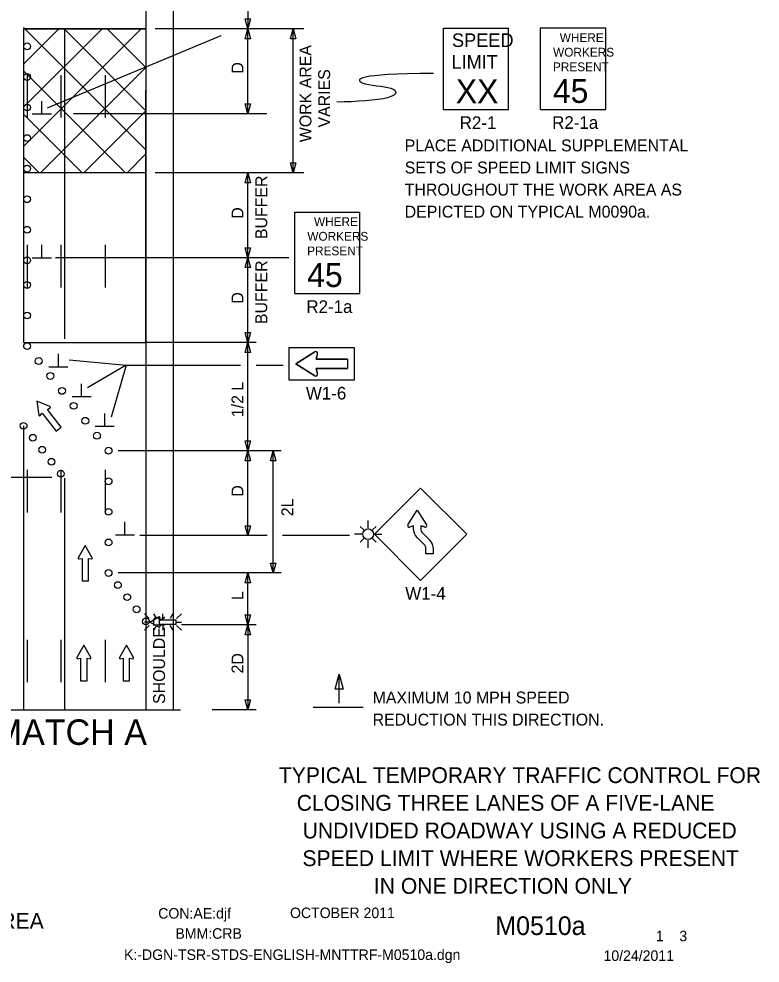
# Model space of a CAD drawing. Extents: x 16730 to 19504, y 5697 to 6911.
# Drawn here: x 17009 to 17445, y 5932 to 6488 of the extents above; entities that cross this region are included whole.
import ezdxf

# ---------------------------------------------------------------- set-up
doc = ezdxf.new("R2010")
doc.units = 0
for name, color, linetype in [('ALI_LEGAL_EX', 7, 'Continuous'), ('BORDER', 7, 'Continuous'), ('BORDER_SIGNAL_WO', 7, 'Continuous'), ('MT_SCRATCH_LEVEL_A', 7, 'Continuous'), ('MT_SCRATCH_LEVEL_E', 7, 'Continuous'), ('PAVT_EDGE_EX', 7, 'Continuous'), ('TRAFFIC_SIGNS_PR', 7, 'Continuous'), ('TYPICAL_TEXT_DIMEN_EX', 7, 'Continuous'), ('TYPICAL_TEXT_DIMEN_PR', 7, 'Continuous')]:
    doc.layers.add(name, color=color, linetype=linetype)

msp = doc.modelspace()

# ---------------------------------------------------------------- linework, layer by layer
at = {"layer": 'ALI_LEGAL_EX'}
for points in [[(17013.43, 6454.77), (17013.43, 6429.77)], [(17033.43, 6454.77), (17033.43, 6429.77)], [(17059.43, 6454.77), (17059.43, 6429.77)], [(17013.43, 6354.77), (17013.43, 6329.77)], [(17033.43, 6354.77), (17033.43, 6329.77)], [(17059.43, 6354.77), (17059.43, 6329.77)], [(17013.43, 6222.28), (17013.43, 6197.28)], [(17033.43, 6222.28), (17033.43, 6197.28)], [(17059.43, 6222.28), (17059.43, 6197.28)], [(17013.43, 6122.28), (17013.43, 6097.28)], [(17033.43, 6122.28), (17033.43, 6097.28)], [(17059.43, 6122.28), (17059.43, 6097.28)]]:
    msp.add_lwpolyline(points, dxfattribs=at)
at = {"layer": 'MT_SCRATCH_LEVEL_A'}
for p, q in [((17083.43, 6410.69), (17011.43, 6482.69)), ((17011.43, 6481.95), (17083.43, 6481.95)), ((17083.43, 6481.95), (17011.43, 6481.95)), ((17011.43, 6412.69), (17080.7, 6481.95)), ((17011.43, 6461.23), (17032.15, 6481.95)), ((17011.43, 6435.78), (17057.61, 6481.95)), ((17083.43, 6433.78), (17035.26, 6481.95)), ((17083.43, 6459.23), (17060.72, 6481.95)), ((17071.44, 6397.23), (17011.43, 6457.24)), ((17021.43, 6397.23), (17083.43, 6459.23)), ((17083.43, 6445.95), (17083.43, 6329.72)), ((17083.43, 6361.78), (17083.43, 6445.95)), ((17046.89, 6397.23), (17083.43, 6433.78)), ((17045.98, 6397.23), (17011.43, 6431.78)), ((17020.53, 6397.23), (17011.43, 6406.33)), ((17072.34, 6397.23), (17083.43, 6408.32))]:
    msp.add_line(p, q, dxfattribs=at)
at = {"layer": 'MT_SCRATCH_LEVEL_E'}
for p, q in [((17019.24, 6262.76), (17020.44, 6254.52)), ((17026.95, 6259.58), (17019.24, 6262.76)), ((17019.24, 6262.76), (17020.44, 6254.52)), ((17026.95, 6259.58), (17019.24, 6262.76)), ((17021.24, 6254.27), (17022.44, 6255.61)), ((17021.24, 6254.27), (17022.44, 6255.61)), ((17022.44, 6255.61), (17030.58, 6245.15)), ((17022.44, 6255.61), (17030.58, 6245.15)), ((17025.4, 6257.91), (17026.99, 6258.75)), ((17025.4, 6257.91), (17026.99, 6258.75)), ((17033.54, 6247.44), (17025.4, 6257.91)), ((17033.54, 6247.44), (17025.4, 6257.91)), ((17030.58, 6245.15), (17033.54, 6247.44)), ((17030.58, 6245.15), (17033.54, 6247.44)), ((17047.71, 6177.79), (17043.6, 6170.55)), ((17047.71, 6177.79), (17043.6, 6170.55)), ((17051.85, 6170.55), (17047.71, 6177.79)), ((17051.85, 6170.55), (17047.71, 6177.79)), ((17044.08, 6169.87), (17045.85, 6170.18)), ((17044.08, 6169.87), (17045.85, 6170.18)), ((17045.85, 6170.18), (17045.85, 6156.93)), ((17045.85, 6170.18), (17045.85, 6156.93)), ((17049.6, 6156.93), (17049.6, 6170.18)), ((17049.6, 6170.18), (17051.37, 6169.87)), ((17049.6, 6156.93), (17049.6, 6170.18)), ((17049.6, 6170.18), (17051.37, 6169.87)), ((17045.85, 6156.93), (17049.6, 6156.93)), ((17045.85, 6156.93), (17049.6, 6156.93)), ((17046.87, 6119.02), (17042.76, 6111.78)), ((17046.87, 6119.02), (17042.76, 6111.78)), ((17051.02, 6111.78), (17046.87, 6119.02)), ((17051.02, 6111.78), (17046.87, 6119.02)), ((17071.96, 6119.02), (17067.85, 6111.78)), ((17071.96, 6119.02), (17067.85, 6111.78)), ((17076.11, 6111.78), (17071.96, 6119.02)), ((17076.11, 6111.78), (17071.96, 6119.02)), ((17043.24, 6111.1), (17045.02, 6111.41)), ((17043.24, 6111.1), (17045.02, 6111.41)), ((17045.02, 6111.41), (17045.02, 6098.16)), ((17045.02, 6111.41), (17045.02, 6098.16)), ((17048.76, 6098.16), (17048.76, 6111.41)), ((17048.76, 6111.41), (17050.54, 6111.1)), ((17048.76, 6098.16), (17048.76, 6111.41)), ((17048.76, 6111.41), (17050.54, 6111.1)), ((17068.33, 6111.1), (17070.11, 6111.41)), ((17068.33, 6111.1), (17070.11, 6111.41)), ((17070.11, 6111.41), (17070.11, 6098.16)), ((17070.11, 6111.41), (17070.11, 6098.16)), ((17073.85, 6098.16), (17073.85, 6111.41)), ((17073.85, 6111.41), (17075.63, 6111.1)), ((17073.85, 6098.16), (17073.85, 6111.41)), ((17073.85, 6111.41), (17075.63, 6111.1)), ((17045.02, 6098.16), (17048.76, 6098.16)), ((17045.02, 6098.16), (17048.76, 6098.16)), ((17070.11, 6098.16), (17073.85, 6098.16)), ((17070.11, 6098.16), (17073.85, 6098.16))]:
    msp.add_line(p, q, dxfattribs=at)
for centre, start, end in [((17026.77, 6259.16), 297.9028, 67.6397), ((17026.77, 6259.16), 297.9028, 67.6397), ((17020.89, 6254.59), 188.2915, 317.8304), ((17020.89, 6254.59), 188.2915, 317.8304), ((17044, 6170.33), 150.4248, 279.9638), ((17044, 6170.33), 150.4248, 279.9638), ((17051.44, 6170.33), 260.0362, 29.7731), ((17051.44, 6170.33), 260.0362, 29.7731), ((17043.17, 6111.56), 150.4248, 279.9638), ((17043.17, 6111.56), 150.4248, 279.9638), ((17050.61, 6111.56), 260.0362, 29.7731), ((17050.61, 6111.56), 260.0362, 29.7731), ((17068.26, 6111.56), 150.4248, 279.9638), ((17068.26, 6111.56), 150.4248, 279.9638), ((17075.7, 6111.56), 260.0362, 29.7731), ((17075.7, 6111.56), 260.0362, 29.7731)]:
    msp.add_arc(centre, 0.463, start, end, dxfattribs=at)
at = {"layer": 'PAVT_EDGE_EX'}
for p, q in [((17083.43, 6911.29), (17083.43, 6081.05)), ((17099.43, 6911.29), (17099.43, 6081.05)), ((17011.43, 6481.95), (17011.43, 6329.72)), ((17035.43, 6481.95), (17035.43, 6299.46)), ((17011.43, 6248.17), (17011.43, 6081.05)), ((17035.43, 6217.31), (17035.43, 6081.05))]:
    msp.add_line(p, q, dxfattribs=at)
msp.add_lwpolyline([(17083.43, 6397.23), (17011.43, 6397.23), (17011.43, 6297.23), (17083.43, 6297.23)], close=True, dxfattribs=at)
at = {"layer": 'TRAFFIC_SIGNS_PR'}
for p, q in [((17258.65, 6482.45), (17297.05, 6482.45)), ((17258.65, 6434.45), (17258.65, 6482.45)), ((17297.05, 6434.45), (17297.05, 6482.45)), ((17315.85, 6482.54), (17354.25, 6482.54)), ((17315.85, 6434.54), (17315.85, 6482.54)), ((17354.25, 6434.54), (17354.25, 6482.54)), ((17258.65, 6434.45), (17297.05, 6434.45)), ((17315.85, 6434.54), (17354.25, 6434.54)), ((17171.11, 6374.13), (17209.51, 6374.13)), ((17171.11, 6326.13), (17171.11, 6374.13)), ((17209.51, 6326.13), (17209.51, 6374.13)), ((17171.11, 6326.13), (17209.51, 6326.13)), ((17182.89, 6291.86), (17171.73, 6284.76)), ((17183.73, 6287.56), (17184.57, 6290.62)), ((17171.73, 6284.76), (17182.89, 6277.65)), ((17202.13, 6287.56), (17183.73, 6287.56)), ((17202.13, 6287.56), (17202.13, 6281.96)), ((17184.57, 6278.9), (17183.73, 6281.96)), ((17183.73, 6281.96), (17202.13, 6281.96)), ((17218.04, 6184.39), (17245.2, 6211.55)), ((17272.35, 6184.39), (17245.2, 6211.55)), ((17211.81, 6186.91), (17209.71, 6189.01)), ((17214.33, 6187.95), (17214.33, 6192.45)), ((17216.84, 6186.91), (17218.95, 6189.01)), ((17211.17, 6184.39), (17206.34, 6184.39)), ((17217.48, 6184.39), (17222.36, 6184.39)), ((17245.2, 6157.24), (17218.04, 6184.39)), ((17272.35, 6184.39), (17245.2, 6157.24)), ((17250.67, 6180.93), (17245.95, 6185.64)), ((17245.95, 6185.64), (17250.67, 6180.93)), ((17211.81, 6181.88), (17209.71, 6179.77)), ((17214.33, 6176.43), (17214.33, 6180.84)), ((17216.84, 6181.88), (17218.95, 6179.77)), ((17247.61, 6177.88), (17242.9, 6182.59)), ((17247.61, 6177.87), (17242.9, 6182.59)), ((17082.56, 6137.53), (17085.38, 6134.72)), ((17088, 6137.54), (17089.21, 6135.44)), ((17093.47, 6134.72), (17093.47, 6137.54)), ((17099.26, 6137.54), (17097.63, 6134.72)), ((17101.55, 6134.72), (17104.38, 6137.54)), ((17085.38, 6132.68), (17082.56, 6132.68)), ((17082.56, 6127.83), (17085.38, 6130.65)), ((17089.29, 6130.02), (17088.03, 6127.83)), ((17093.47, 6130.65), (17093.47, 6127.83)), ((17097.6, 6130.65), (17099.23, 6127.83)), ((17101.55, 6132.68), (17104.38, 6132.68)), ((17101.55, 6130.65), (17104.38, 6127.83))]:
    msp.add_line(p, q, dxfattribs=at)
msp.add_lwpolyline([(17206.13, 6275.16), (17167.73, 6275.16), (17167.73, 6294.36), (17206.13, 6294.36)], close=True, dxfattribs=at)
for points in [[(17182.89, 6277.65), (17171.73, 6284.76), (17182.89, 6291.86)], [(17184.57, 6290.62), (17183.73, 6287.56), (17202.13, 6287.56), (17202.13, 6281.96), (17183.73, 6281.96), (17184.57, 6278.9)], [(17237.74, 6189.92), (17243.23, 6198.53), (17248.71, 6189.92)], [(17237.75, 6189.92), (17243.23, 6198.53), (17248.71, 6189.92)], [(17241.08, 6186.9), (17241.07, 6189.27), (17238.71, 6188.62)], [(17241.08, 6186.9), (17241.07, 6189.27), (17238.71, 6188.62)], [(17247.75, 6188.62), (17245.39, 6189.27), (17245.39, 6186.97)], [(17247.75, 6188.62), (17246.91, 6188.85), (17245.39, 6189.27), (17245.39, 6186.97)], [(17252.53, 6176.51), (17252.53, 6172.81), (17248.22, 6172.81), (17248.22, 6176.51)], [(17091.14, 6129.67), (17085.83, 6132.68), (17091.14, 6135.73)], [(17091.64, 6135.37), (17091.41, 6134.07), (17101.14, 6134.07), (17101.14, 6131.33), (17091.41, 6131.33), (17091.64, 6130.02)]]:
    msp.add_lwpolyline(points, dxfattribs=at)
for centre, radius in [((17013.46, 6471.67), 2), ((17013.46, 6453.67), 2), ((17013.46, 6435.67), 2), ((17013.46, 6417.67), 2), ((17013.46, 6399.67), 2), ((17013.46, 6381.67), 2), ((17013.46, 6363.67), 2), ((17013.46, 6345.67), 2), ((17013.46, 6331.18), 2), ((17013.46, 6313.18), 2), ((17013.46, 6295.18), 2), ((17013.46, 6295.18), 2), ((17020.32, 6286.39), 2), ((17027.17, 6277.59), 2), ((17034.03, 6268.8), 2), ((17040.89, 6260), 2), ((17011.38, 6248.24), 2), ((17047.74, 6251.21), 2), ((17054.6, 6242.41), 2), ((17016.87, 6241.19), 2), ((17022.35, 6234.13), 2), ((17061.46, 6233.57), 2), ((17061.46, 6233.57), 2), ((17027.84, 6227.07), 2), ((17033.32, 6220.02), 2), ((17061.46, 6215.57), 2), ((17061.46, 6197.57), 2), ((17214.33, 6184.39), 3.15), ((17061.46, 6179.57), 2), ((17061.46, 6161.57), 2), ((17066.95, 6154.43), 2), ((17072.45, 6147.31), 2), ((17077.95, 6140.18), 2), ((17083.45, 6133.05), 2)]:
    msp.add_circle(centre, radius, dxfattribs=at)
for centre, radius, start, end in [((17183.49, 6290.91), 1.12, 344.6731, 122.4696), ((17183.49, 6290.91), 1.12, 344.6731, 122.4696), ((17183.49, 6278.6), 1.12, 237.5304, 15.3269), ((17183.49, 6278.6), 1.12, 237.5304, 15.3269), ((17238.48, 6189.45), 0.866, 147.7292, 285.3172), ((17238.48, 6189.45), 0.866, 147.7196, 285.3201), ((17228.64, 6195.71), 10.8, 327.5335, 327.5431), ((17241.56, 6178.2), 10.8, 105.3192, 105.32), ((17247.98, 6189.45), 0.866, 254.6148, 32.4712), ((17247.24, 6186.97), 6.17, 180.6181, 225.7875), ((17247.24, 6186.97), 6.17, 180.6245, 225.2313), ((17247.24, 6186.97), 1.85, 180, 225.7875), ((17247.24, 6186.97), 1.85, 179.8762, 225.7877), ((17246.37, 6176.51), 1.85, 0, 47.628), ((17246.37, 6176.51), 6.17, 0, 45.7883), ((17091.31, 6135.43), 0.341, 350.0407, 118.5167), ((17091.31, 6129.97), 0.341, 241.1084, 9.2692)]:
    msp.add_arc(centre, radius, start, end, dxfattribs=at)
at = {"layer": 'TYPICAL_TEXT_DIMEN_PR'}
for p, q in [((17143.43, 6506.95), (17143.43, 6481.95)), ((17143.43, 6481.95), (17141.86, 6487.81)), ((17141.86, 6487.81), (17143.43, 6487.81)), ((17143.43, 6487.81), (17145, 6487.81)), ((17145, 6487.81), (17143.43, 6481.95)), ((17127.61, 6477.78), (17025.37, 6435.27)), ((17176.35, 6481.95), (17088.94, 6481.95)), ((17141.86, 6476.09), (17143.43, 6481.95)), ((17143.43, 6431.95), (17143.43, 6482.6)), ((17143.43, 6481.95), (17145, 6476.09)), ((17168.68, 6476.09), (17170.25, 6481.95)), ((17170.25, 6397.23), (17170.25, 6481.95)), ((17170.25, 6481.95), (17171.82, 6476.09)), ((17143.43, 6476.09), (17141.86, 6476.09)), ((17145, 6476.09), (17143.43, 6476.09)), ((17170.25, 6476.09), (17168.68, 6476.09)), ((17171.82, 6476.09), (17170.25, 6476.09)), ((17022.13, 6431.72), (17022.13, 6439.5)), ((17143.43, 6431.95), (17141.86, 6437.81)), ((17141.86, 6437.81), (17143.43, 6437.81)), ((17143.43, 6437.81), (17145.01, 6437.81)), ((17145.01, 6437.81), (17143.43, 6431.95)), ((17027.76, 6431.72), (17016.51, 6431.72)), ((17154.74, 6431.95), (17040.71, 6431.95)), ((17170.25, 6397.23), (17168.68, 6403.09)), ((17168.68, 6403.09), (17170.25, 6403.09)), ((17170.25, 6403.09), (17171.82, 6403.09)), ((17171.82, 6403.09), (17170.25, 6397.23)), ((17176.35, 6397.23), (17088.94, 6397.23)), ((17141.86, 6391.37), (17143.43, 6397.23)), ((17143.43, 6347.23), (17143.43, 6397.23)), ((17143.43, 6397.23), (17145, 6391.37)), ((17143.43, 6391.37), (17141.86, 6391.37)), ((17145, 6391.37), (17143.43, 6391.37)), ((17022.13, 6347), (17022.13, 6354.78)), ((17143.43, 6347.23), (17141.86, 6353.09)), ((17141.86, 6353.09), (17143.43, 6353.09)), ((17143.43, 6353.09), (17145.01, 6353.09)), ((17145.01, 6353.09), (17143.43, 6347.23)), ((17027.76, 6347), (17016.51, 6347)), ((17167.54, 6347.23), (17030.11, 6347.23)), ((17141.86, 6341.37), (17143.43, 6347.23)), ((17143.43, 6297.23), (17143.43, 6347.23)), ((17143.43, 6347.23), (17145, 6341.37)), ((17143.43, 6341.37), (17141.86, 6341.37)), ((17145, 6341.37), (17143.43, 6341.37)), ((17143.43, 6297.23), (17141.86, 6303.09)), ((17141.86, 6303.09), (17143.43, 6303.09)), ((17143.43, 6303.09), (17145.01, 6303.09)), ((17145.01, 6303.09), (17143.43, 6297.23)), ((17148.43, 6297.23), (17083.43, 6297.23)), ((17141.86, 6291.37), (17143.43, 6297.23)), ((17143.43, 6297.23), (17145, 6291.37)), ((17143.43, 6233.57), (17143.43, 6297.23)), ((17031.92, 6282.74), (17031.92, 6290.53)), ((17143.43, 6291.37), (17141.86, 6291.37)), ((17145, 6291.37), (17143.43, 6291.37)), ((17038.26, 6287.13), (17071.9, 6284.04)), ((17071.9, 6284.04), (17048.96, 6270.57)), ((17071.9, 6284.04), (17063.03, 6253.39)), ((17071.9, 6284.04), (17139.16, 6284.04)), ((17148.33, 6284.04), (17164.23, 6284.04)), ((17037.54, 6282.74), (17026.29, 6282.74)), ((17045.55, 6265.25), (17045.55, 6273.03)), ((17051.17, 6265.25), (17039.92, 6265.25)), ((17059.17, 6247.75), (17059.17, 6255.54)), ((17064.8, 6247.75), (17053.55, 6247.75)), ((17143.43, 6233.57), (17141.86, 6239.43)), ((17141.86, 6239.43), (17143.43, 6239.43)), ((17143.43, 6239.43), (17145, 6239.43)), ((17145, 6239.43), (17143.43, 6233.57)), ((17163.01, 6233.57), (17067.2, 6233.57)), ((17141.86, 6227.7), (17143.43, 6233.57)), ((17143.43, 6183.57), (17143.43, 6233.57)), ((17143.43, 6233.57), (17145, 6227.7)), ((17156.86, 6227.7), (17158.43, 6233.57)), ((17158.43, 6161.57), (17158.43, 6233.57)), ((17158.43, 6233.57), (17160.01, 6227.7)), ((17143.43, 6227.7), (17141.86, 6227.7)), ((17145, 6227.7), (17143.43, 6227.7)), ((17158.43, 6227.7), (17156.86, 6227.7)), ((17160.01, 6227.7), (17158.43, 6227.7)), ((16898.34, 6218.03), (17027.97, 6218.03)), ((17071.1, 6183.92), (17071.1, 6191.71)), ((17143.43, 6183.57), (17141.86, 6189.43)), ((17141.86, 6189.43), (17143.43, 6189.43)), ((17143.43, 6189.43), (17145.01, 6189.43)), ((17145.01, 6189.43), (17143.43, 6183.57)), ((17076.72, 6183.92), (17065.47, 6183.92)), ((17154.76, 6183.57), (17079.85, 6183.57)), ((17203.37, 6183.57), (17163.93, 6183.57)), ((17158.43, 6161.57), (17156.86, 6167.43)), ((17156.86, 6167.43), (17158.43, 6167.43)), ((17158.43, 6167.43), (17160.01, 6167.43)), ((17160.01, 6167.43), (17158.43, 6161.57)), ((17163.01, 6161.57), (17067.2, 6161.57)), ((17141.86, 6155.7), (17143.43, 6161.57)), ((17143.43, 6131.05), (17143.43, 6161.57)), ((17143.43, 6161.57), (17145, 6155.7)), ((17143.43, 6155.7), (17141.86, 6155.7)), ((17145, 6155.7), (17143.43, 6155.7)), ((17143.43, 6131.05), (17141.86, 6136.92)), ((17141.86, 6136.92), (17143.43, 6136.92)), ((17143.43, 6136.92), (17145, 6136.92)), ((17145, 6136.92), (17143.43, 6131.05)), ((17148.43, 6131.05), (17104.45, 6131.05)), ((17141.86, 6125.19), (17143.43, 6131.05)), ((17143.43, 6131.05), (17145, 6125.19)), ((17143.43, 6131.05), (17143.43, 6081.05)), ((17143.43, 6125.19), (17141.86, 6125.19)), ((17145, 6125.19), (17143.43, 6125.19)), ((17194.9, 6093.15), (17197.25, 6101.94)), ((17197.25, 6084.82), (17197.25, 6101.95)), ((17197.25, 6101.94), (17199.61, 6093.15)), ((17197.25, 6093.15), (17194.9, 6093.15)), ((17199.61, 6093.15), (17197.25, 6093.15)), ((17143.43, 6081.05), (17141.86, 6086.92)), ((17141.86, 6086.92), (17143.43, 6086.92)), ((17143.43, 6086.92), (17145, 6086.92)), ((17145, 6086.92), (17143.43, 6081.05)), ((16943.13, 6081.05), (17103.73, 6081.05)), ((17148.43, 6081.05), (17122.43, 6081.05)), ((17211.43, 6082.32), (17181.99, 6082.32))]:
    msp.add_line(p, q, dxfattribs=at)
msp.add_open_spline([(17252.78, 6455.66), (17206.68, 6455.66), (17206.68, 6448.39), (17231.86, 6448.39), (17231.86, 6440.43), (17207.14, 6439.06), (17195.82, 6438.82)], degree=3, dxfattribs=at)

# ---------------------------------------------------------------- texts
at = {"layer": 'BORDER'}
for s, p in [('TYPICAL TEMPORARY TRAFFIC CONTROL FOR', (17161.75, 6037.86)), ('CLOSING THREE LANES OF A FIVE-LANE', (17172.26, 6021.56)), ('UNDIVIDED ROADWAY USING A REDUCED', (17175.72, 6005.26)), ('SPEED LIMIT WHERE WORKERS PRESENT', (17175.62, 5988.96)), ('IN ONE DIRECTION ONLY', (17217.69, 5972.66))]:
    msp.add_text(s, height=9.3, dxfattribs=at).set_placement(p)
at = {"layer": 'BORDER_SIGNAL_WO'}
for s, height, p in [('CON:AE:djf', 6.2, (17090.69, 5958.06)), ('    OCTOBER 2011    ', 6.2, (17159.08, 5958.34)), ('    M0510a   ', 11, (17272.86, 5948.38)), ('BMM:CRB   ', 6.2, (17100.81, 5946.17)), (' 1    3 ', 6.2, (17381.45, 5944.7)), ('K:-DGN-TSR-STDS-ENGLISH-MNTTRF-M0510a.dgn        ', 6.2, (17070.55, 5933.71)), ('10/24/2011    ', 6.2, (17352.93, 5933.13))]:
    msp.add_text(s, height=height, dxfattribs=at).set_placement(p)
at = {"layer": 'TRAFFIC_SIGNS_PR'}
for s, height, p in [('SPEED', 8, (17263.68, 6471.31)), ('WHERE', 5.2, (17327.16, 6474.22)), ('LIMIT', 8, (17263.35, 6458.51)), ('WORKERS', 5.2, (17323.23, 6465.62)), ('PRESENT', 5.2, (17323.16, 6457.02)), ('XX', 14.031, (17265.96, 6438.21)), ('45', 14.031, (17323.15, 6438.39)), ('R2-1', 7.44, (17268.26, 6423.01)), ('R2-1a', 7.44, (17322.7, 6423.1)), ('PLACE ADDITIONAL SUPPLEMENTAL', 7, (17235.85, 6409.84)), ('SETS OF SPEED LIMIT SIGNS', 7, (17235.85, 6396.84)), ('THROUGHOUT THE WORK AREA AS', 7, (17235.85, 6383.84)), ('DEPICTED ON TYPICAL M0090a.', 7, (17235.85, 6370.84)), ('WHERE', 5.2, (17182.42, 6365.82)), ('WORKERS', 5.2, (17178.49, 6357.22)), ('PRESENT', 5.2, (17178.42, 6348.62)), ('45', 14.031, (17178.41, 6329.99)), ('R2-1a', 7.44, (17177.96, 6314.69)), ('W1-6', 7.44, (17177.67, 6263.72)), ('W1-4', 7.44, (17236.2, 6145.8))]:
    msp.add_text(s, height=height, dxfattribs=at).set_placement(p)
at = {"layer": 'TYPICAL_TEXT_DIMEN_EX'}
msp.add_text('SIGNING THROUGHOUT WORK AREA', height=9.3, dxfattribs=at).set_placement((16798.75, 5952.05))
at = {"layer": 'TYPICAL_TEXT_DIMEN_PR'}
for s, p in [('WORK AREA', (17180.92, 6415.24)), ('D', (17140.88, 6455.61)), ('VARIES', (17191.92, 6423.89)), ('BUFFER', (17154.89, 6358.16)), ('D', (17140.88, 6370.17)), ('BUFFER', (17154.89, 6308.16)), ('D', (17140.88, 6320.17)), ('1/2 L', (17140.88, 6253.34)), ('D', (17140.88, 6206.51)), ('2L', (17170.23, 6194.99)), ('L', (17140.88, 6145.67)), ('SHOULDER', (17094.71, 6084.43)), ('2D', (17140.88, 6102.4))]:
    msp.add_text(s, height=7, rotation=90, dxfattribs=at).set_placement(p)
for s, height, p in [('MAXIMUM 10 MPH SPEED', 7, (17216.95, 6084.74)), ('REDUCTION THIS DIRECTION.', 7, (17216.95, 6071.74)), ('A MATCH A', 15, (16974.85, 6060.35))]:
    msp.add_text(s, height=height, dxfattribs=at).set_placement(p)

doc.saveas('drawing.dxf')
